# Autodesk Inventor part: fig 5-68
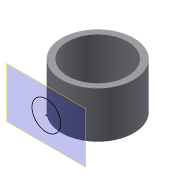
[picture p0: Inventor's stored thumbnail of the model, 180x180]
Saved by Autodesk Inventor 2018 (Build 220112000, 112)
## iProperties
Shininess: 64.0
Length Units: 11269
Angle Units: 11279
Time Units: 11290
Mass Units: 11283
Length Display Precision: 3
Angle Display Precision: 2
Compacted: True
Part Number: fig 5-68
Document SubType Name: Modeling
Created: 2002-12
Designer: deepak
Density: 1 g/cm^3
Material: Generic
Appearance: Default
Density: 0.0
Volumn: 0.0
Area: 0.0
PropertySet Name: Model Information
Control State: 0
Master: False
Checked Out: False
Author: deepak
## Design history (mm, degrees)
sketch "Sketch1"
  geometry: C1 r 23.454 at (0, 0); C2 r 19.43 at (0, 0)
  constraints: 2 centre point, 1 coincident, 1 concentric
extrude "Extrusion1" new body sketch "Sketch1" stored distance "d0" = 30; taper "d1" = 0 deg
workplane "Work Plane1"
workplane "Work Plane2"
sketch "Sketch2"
  geometry: C1 r 9.343 at (0, 0)
  constraints: 1 centre point
body "Solid1"
